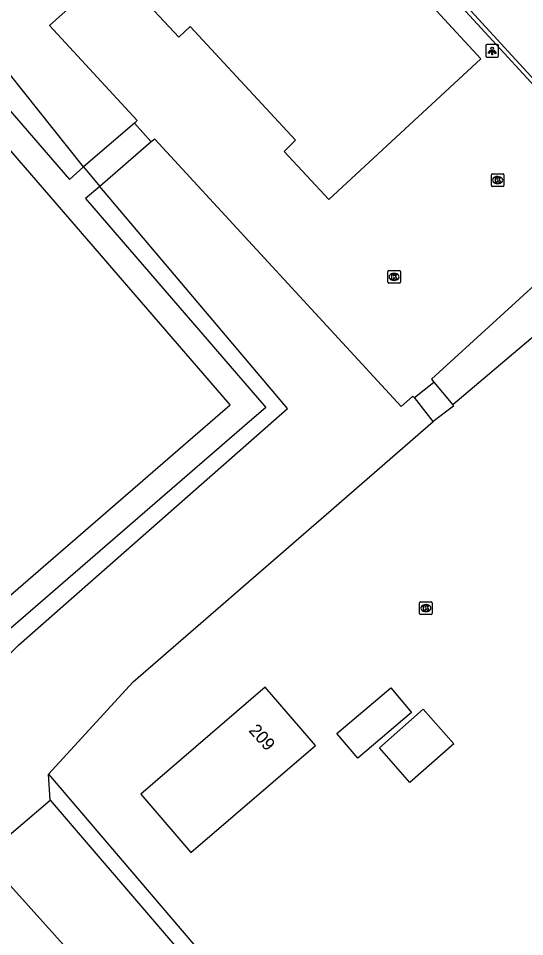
# Model space of a CAD drawing. Extents: x 156061 to 157804, y 383451 to 385640.
# Drawn here: x 157614.8 to 157655, y 383596.7 to 383669.5 of the extents above; entities that cross this region are included whole.
import ezdxf

# ---------------------------------------------------------------- set-up
doc = ezdxf.new("R2010")
doc.units = 0
for name, color, linetype in [('IMGEO_Grasland_overig', 7, 'Continuous'), ('IMGEO_Groenvoorziening', 7, 'Continuous'), ('IMGEO_Kolk', 7, 'Continuous'), ('IMGEO_Lichtpunt', 7, 'Continuous'), ('IMGEO_Meer_plas_ven_vijver', 7, 'Continuous'), ('IMGEO_Pand', 7, 'Continuous'), ('IMGEO_Pand_nummerreeks', 7, 'Continuous'), ('IMGEO_Rijbaan_lokaal_gesloten', 7, 'Continuous'), ('IMGEO_Rijbaan_lokaal_open', 7, 'Continuous'), ('IMGEO_Voetpad_gesloten', 7, 'Continuous')]:
    doc.layers.add(name, color=color, linetype=linetype)

msp = doc.modelspace()

# ---------------------------------------------------------------- linework, layer by layer
at = {"layer": 'IMGEO_Grasland_overig'}
for points in [[(157636.298, 383685.833), (157635.64, 383685.18), (157622.846, 383673.301), (157622.498, 383673.653), (157617.28, 383668.944), (157624.23, 383661.417), (157624.003, 383661.197)], [(157609.282, 383671.12), (157607.636, 383669.704), (157608.419, 383668.784), (157618.847, 383656.716), (157619.968, 383657.726)], [(157619.968, 383657.726), (157609.282, 383671.12)], [(157617.318, 383607.508), (157617.189, 383609.565)], [(157617.189, 383609.565), (157665.287, 383553.229)], [(157617.318, 383607.508), (157666.014, 383550.759)]]:
    msp.add_lwpolyline(points, dxfattribs=at)
at = {"layer": 'IMGEO_Groenvoorziening'}
for points in [[(157646.224, 383639.429), (157646.075, 383639.53), (157645.162, 383638.719), (157625.613, 383659.933), (157625.333, 383659.711)], [(157621.256, 383656.181), (157620.132, 383655.218), (157634.437, 383638.653), (157632.931, 383637.35), (157596.405, 383605.765)], [(157598.3, 383603.675), (157614.798, 383619.797), (157633.728, 383636.44), (157636.145, 383638.565), (157621.256, 383656.181)], [(157663.038, 383655.013), (157647.565, 383640.888), (157647.765, 383640.669)], [(157669.22, 383644.961), (157663.882, 383651.218), (157649.251, 383638.856)], [(157617.189, 383609.565), (157623.911, 383616.901), (157639.22, 383630.176), (157647.699, 383637.528)], [(157630.214, 383582.846), (157612.047, 383603.052), (157617.318, 383607.508)]]:
    msp.add_lwpolyline(points, dxfattribs=at)
at = {"layer": 'IMGEO_Kolk'}
for p, q in [((157652.319, 383656.255), (157652.319, 383657.107)), ((157652.394, 383657.181), (157653.246, 383657.181)), ((157652.807, 383656.961), (157652.832, 383656.961)), ((157653.32, 383657.107), (157653.32, 383656.255)), ((157653.246, 383656.181), (157652.394, 383656.181)), ((157652.83, 383656.401), (157652.805, 383656.401)), ((157644.102, 383648.579), (157644.102, 383649.431)), ((157644.177, 383649.505), (157645.029, 383649.505)), ((157644.59, 383649.285), (157644.615, 383649.285)), ((157645.103, 383649.431), (157645.103, 383648.579)), ((157644.613, 383648.725), (157644.588, 383648.725)), ((157645.029, 383648.505), (157644.177, 383648.505)), ((157646.629, 383622.314), (157646.629, 383623.166)), ((157646.704, 383623.24), (157647.556, 383623.24)), ((157647.63, 383623.166), (157647.63, 383622.314)), ((157647.14, 383622.46), (157647.115, 383622.46)), ((157647.117, 383623.02), (157647.142, 383623.02)), ((157647.556, 383622.24), (157646.704, 383622.24))]:
    msp.add_line(p, q, dxfattribs=at)
for points in [[(157652.319, 383656.255), (157652.319, 383657.107)], [(157652.394, 383657.181), (157653.246, 383657.181)], [(157652.64, 383656.881), (157652.763, 383656.881), (157652.763, 383656.73), (157652.893, 383656.881), (157653.057, 383656.881), (157652.911, 383656.73), (157653.064, 383656.481), (157652.912, 383656.481), (157652.827, 383656.645), (157652.763, 383656.578), (157652.763, 383656.481), (157652.64, 383656.481), (157652.64, 383656.881)], [(157653.32, 383657.107), (157653.32, 383656.255)], [(157653.246, 383656.181), (157652.394, 383656.181)], [(157644.102, 383648.579), (157644.102, 383649.431)], [(157644.177, 383649.505), (157645.029, 383649.505)], [(157645.103, 383649.431), (157645.103, 383648.579)], [(157644.423, 383649.205), (157644.546, 383649.205), (157644.546, 383649.054), (157644.676, 383649.205), (157644.84, 383649.205), (157644.694, 383649.054), (157644.847, 383648.805), (157644.695, 383648.805), (157644.61, 383648.969), (157644.546, 383648.902), (157644.546, 383648.805), (157644.423, 383648.805), (157644.423, 383649.205)], [(157645.029, 383648.505), (157644.177, 383648.505)], [(157646.629, 383622.314), (157646.629, 383623.166)], [(157646.704, 383623.24), (157647.556, 383623.24)], [(157647.63, 383623.166), (157647.63, 383622.314)], [(157646.95, 383622.94), (157647.073, 383622.94), (157647.073, 383622.789), (157647.203, 383622.94), (157647.367, 383622.94), (157647.221, 383622.789), (157647.374, 383622.54), (157647.222, 383622.54), (157647.137, 383622.704), (157647.073, 383622.637), (157647.073, 383622.54), (157646.95, 383622.54), (157646.95, 383622.94)], [(157647.556, 383622.24), (157646.704, 383622.24)]]:
    msp.add_lwpolyline(points, dxfattribs=at)
for centre, start, end in [((157652.396, 383657.105), 91.55205, 178.44795), ((157652.396, 383657.105), 91.55205, 178.44795), ((157653.244, 383657.105), 1.55205, 88.44795), ((157653.244, 383657.105), 1.55205, 88.44795), ((157652.396, 383656.257), 181.55205, 268.44795), ((157652.396, 383656.257), 181.55205, 268.44795), ((157653.244, 383656.257), 271.55205, 358.44795), ((157653.244, 383656.257), 271.55205, 358.44795), ((157644.179, 383649.429), 91.55205, 178.44795), ((157644.179, 383649.429), 91.55205, 178.44795), ((157645.027, 383649.429), 1.55205, 88.44795), ((157645.027, 383649.429), 1.55205, 88.44795), ((157644.179, 383648.581), 181.55205, 268.44795), ((157644.179, 383648.581), 181.55205, 268.44795), ((157645.027, 383648.581), 271.55205, 358.44795), ((157645.027, 383648.581), 271.55205, 358.44795), ((157646.706, 383623.164), 91.55205, 178.44795), ((157646.706, 383623.164), 91.55205, 178.44795), ((157647.554, 383623.164), 1.55205, 88.44795), ((157647.554, 383623.164), 1.55205, 88.44795), ((157646.706, 383622.316), 181.55205, 268.44795), ((157646.706, 383622.316), 181.55205, 268.44795), ((157647.554, 383622.316), 271.55205, 358.44795), ((157647.554, 383622.316), 271.55205, 358.44795)]:
    msp.add_arc(centre, 0.0765, start, end, dxfattribs=at)
for centre, major_axis, ratio, start_param, end_param in [((157652.806, 383656.681), (-0.387, 0.002), 0.722429, 4.712389, 7.853982), ((157652.831, 383656.681), (-0.39, 0.002), 0.717154, 1.570796, 4.712389), ((157644.589, 383649.005), (-0.387, 0.002), 0.722429, 4.712389, 7.853982), ((157644.614, 383649.005), (-0.39, 0.002), 0.717154, 1.570796, 4.712389), ((157647.116, 383622.74), (-0.387, 0.002), 0.722429, 4.712389, 7.853982), ((157647.141, 383622.74), (-0.39, 0.002), 0.717154, 1.570796, 4.712389)]:
    msp.add_ellipse(centre, major_axis=major_axis, ratio=ratio, start_param=start_param, end_param=end_param, dxfattribs=at)
at = {"layer": 'IMGEO_Lichtpunt'}
for p, q in [((157651.885, 383667.331), (157651.885, 383666.524)), ((157651.885, 383667.331), (157651.885, 383666.524)), ((157652.787, 383667.426), (157651.979, 383667.426)), ((157652.787, 383667.426), (157651.979, 383667.426)), ((157652.881, 383666.524), (157652.881, 383667.331)), ((157652.881, 383666.524), (157652.881, 383667.331)), ((157651.979, 383666.43), (157652.787, 383666.43)), ((157651.979, 383666.43), (157652.787, 383666.43))]:
    msp.add_line(p, q, dxfattribs=at)
for points in [[(157652.259, 383666.995), (157652.298, 383666.967), (157652.11, 383666.705), (157652.072, 383666.732), (157652.259, 383666.995)], [(157652.361, 383666.947), (157652.408, 383666.947), (157652.408, 383666.625), (157652.361, 383666.625), (157652.361, 383666.947)], [(157652.471, 383666.967), (157652.509, 383666.994), (157652.696, 383666.732), (157652.657, 383666.704), (157652.471, 383666.967)]]:
    msp.add_lwpolyline(points, dxfattribs=at)
msp.add_circle((157652.384, 383667.129), 0.0994, dxfattribs=at)
for centre, start, end in [((157651.979, 383667.331), 90, 180), ((157651.979, 383667.331), 90, 180), ((157652.787, 383667.331), 0, 90), ((157652.787, 383667.331), 0, 90), ((157651.979, 383666.524), 180, 270), ((157651.979, 383666.524), 180, 270), ((157652.787, 383666.524), 270, 0), ((157652.787, 383666.524), 270, 360)]:
    msp.add_arc(centre, 0.0946, start, end, dxfattribs=at)
at = {"layer": 'IMGEO_Meer_plas_ven_vijver'}
msp.add_lwpolyline([(157595.061, 383607.241), (157603.332, 383614.398), (157604.478, 383615.391), (157631.604, 383638.864), (157592.743, 383683.81), (157592.085, 383684.583), (157589.969, 383686.975), (157584.203, 383693.494), (157593.316, 383701.326), (157589.181, 383706.103), (157580.09, 383698.235), (157574.434, 383704.864), (157569.551, 383710.587), (157546.586, 383690.669), (157545.842, 383690.024), (157536.954, 383682.315)], dxfattribs=at)
at = {"layer": 'IMGEO_Pand'}
for points in [[(157639.423, 383655.14), (157635.882, 383658.959), (157636.783, 383659.847), (157628.424, 383668.849), (157627.528, 383668.013), (157624.022, 383671.797), (157636.09, 383682.98), (157637.392, 383681.569), (157651.485, 383666.295), (157639.423, 383655.14)], [(157628.488, 383603.368), (157638.361, 383611.855), (157634.384, 383616.48), (157624.511, 383607.993), (157628.488, 383603.368)], [(157641.73, 383610.838), (157640.071, 383612.794), (157644.334, 383616.41), (157645.994, 383614.453), (157641.73, 383610.838)], [(157645.865, 383608.915), (157643.438, 383611.664), (157646.918, 383614.736), (157649.345, 383611.987), (157645.865, 383608.915)]]:
    msp.add_lwpolyline(points, dxfattribs=at)
at = {"layer": 'IMGEO_Rijbaan_lokaal_gesloten'}
msp.add_lwpolyline([(157681.542, 383607.66), (157681.915, 383611.645), (157682.248, 383616.298), (157682.165, 383620.962), (157681.665, 383625.6), (157680.752, 383630.175), (157680.657, 383630.556), (157679.272, 383634.513), (157677.539, 383638.33), (157675.471, 383641.977), (157673.087, 383645.425), (157670.403, 383648.646), (157670.038, 383649.042), (157640.558, 383681.144), (157639.039, 383682.875), (157636.942, 383685.511), (157634.822, 383688.528), (157632.775, 383691.884), (157631.195, 383694.874), (157629.704, 383698.154), (157609.012, 383750), (157585.847, 383808.044)], dxfattribs=at)
at = {"layer": 'IMGEO_Rijbaan_lokaal_open'}
msp.add_lwpolyline([(157636.298, 383685.833), (157642.073, 383679.016), (157649.055, 383671.421), (157652.735, 383667.414), (157663.63, 383655.554)], dxfattribs=at)
at = {"layer": 'IMGEO_Voetpad_gesloten'}
for points in [[(157624.003, 383661.197), (157619.968, 383657.726)], [(157624.003, 383661.197), (157625.333, 383659.711)], [(157625.333, 383659.711), (157621.256, 383656.181)], [(157619.968, 383657.726), (157621.256, 383656.181)], [(157646.224, 383639.429), (157647.765, 383640.669)], [(157647.765, 383640.669), (157649.251, 383638.856)], [(157647.699, 383637.528), (157646.224, 383639.429)], [(157649.251, 383638.856), (157649.329, 383638.753), (157647.699, 383637.528)]]:
    msp.add_lwpolyline(points, dxfattribs=at)

# ---------------------------------------------------------------- texts
at = {"layer": 'IMGEO_Pand_nummerreeks'}
msp.add_text('209', height=1, rotation=311.98721, dxfattribs=at).set_placement((157633.019, 383613))

doc.saveas('drawing.dxf')
